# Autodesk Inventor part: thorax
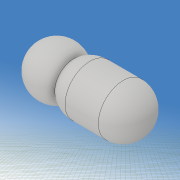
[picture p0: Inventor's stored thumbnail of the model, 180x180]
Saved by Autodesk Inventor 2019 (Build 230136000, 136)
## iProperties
Created: 2021-05
Part Number: thorax
Material: 一般
Document SubType Name: Modeling
Designer: kikut
Density: 1 g/cm^3
Appearance: 既定
Author: kikut
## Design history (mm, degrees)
sketch "スケッチ4"
  geometry: L1 (7, -5)-(1, -5); L2 (12.3, 0)-(-24.8, 0) reference; L3 (0, -15.35)-(0, 31.753) reference; L4 (-19.5, 0.3)-(-2.073, 0.3) reference; L5 (3, -5)-(-7, -5); L6 (0, -8)-(-4, -8); L7 (-5.09, 6.534)-(-4.607, 25.024); A1 r 3 centre (4, -5) between (1, -5) and (7, -5); A2 r 3 centre (0, -5) between (0, -8) and (3, -5); A3 r 3 centre (-4, -5) between (-7, -5) and (-4, -8); 1 further point
  constraints: 8 end point, 6 point on circle, 3 centre point, 2 horizontal, 2 point on line
  dimensions: "d33" = 5 distance between parallel lines of L1 L2; "d34" = 0 vertical distance of L1.start A1.centre; "d35" = 3 radius of A1; "d36" = 1 distance from line of L3 L1.end; "d45" = 0 vertical distance of L6.end L6.start; "d46" = 3 radius of A2; "d47" = 0 distance between parallel lines of L5 L1; "d48" = 4 distance of A1.centre A2.centre; "d49" = 0 horizontal distance of A3.centre L6.end; "d50" = 4 distance of L6.start L6.end
revolve "回転1" sketch "スケッチ4" stored, may be unused: angle "d51" = 90 deg
node "ソリッド1"
